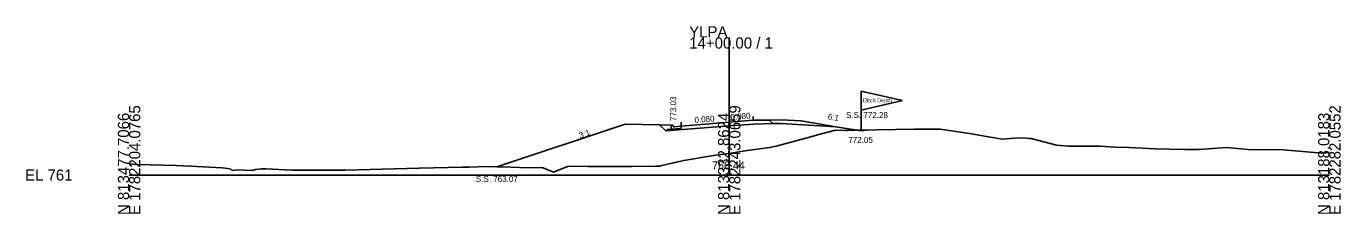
# Model space of a CAD drawing. Extents: x -76 to 1303, y -10 to 9544.
# Drawn here: x -25.7 to 302.8, y 3990.3 to 4037.3 of the extents above; entities that cross this region are included whole.
import ezdxf

# ---------------------------------------------------------------- set-up
doc = ezdxf.new("R2010")
doc.units = 0
for name, color, linetype in [('Exist Cross Section Cell', 7, 'Continuous'), ('Exist XS Center Line Elevation Label', 7, 'Continuous'), ('Exist XS Ground Line', 7, 'Continuous'), ('Prop XS Ditch Slope Text', 7, 'Continuous'), ('Prop XS Ditch Standard Text', 7, 'Continuous'), ('Prop XS Dump Level', 7, 'Continuous'), ('Prop XS Earthwork Shape', 7, 'Continuous'), ('Prop XS EOT Tick Mark', 7, 'Continuous'), ('Prop XS Finish Grade', 7, 'Continuous'), ('Prop XS Finish Grade CurbGutter', 7, 'Continuous'), ('Prop XS Finish Grade Earthwork', 7, 'Continuous'), ('Prop XS Finish Grade Paved Shoulder', 7, 'Continuous'), ('Prop XS Finish Grade Pavement', 7, 'Continuous'), ('Prop XS Hydro Elevations', 7, 'Continuous'), ('Prop XS Hydro Typical Ditch Data', 7, 'Continuous'), ('Prop XS Pvmt Edge Slope', 7, 'Continuous'), ('Prop XS SE Text', 7, 'Continuous'), ('Prop XS Side Slope Text', 7, 'Continuous'), ('Prop XS SS Elevation Text', 7, 'Continuous'), ('Prop XS Subgrade CurbGutter', 7, 'Continuous'), ('Prop XS Subgrade Earthwork', 7, 'Continuous'), ('Scratch_Level_3', 7, 'Continuous')]:
    doc.layers.add(name, color=color, linetype=linetype)

msp = doc.modelspace()

# ---------------------------------------------------------------- linework, layer by layer
at = {"layer": 'Exist Cross Section Cell'}
for p, q in [((150, 4000), (150, 4034.48)), ((0, 4000), (150, 4000)), ((150, 4000), (300, 4000))]:
    msp.add_line(p, q, dxfattribs=at)
at = {"layer": 'Exist XS Ground Line'}
for p, q in [((182.34, 4011.24), (196.26, 4011.49)), ((196.26, 4011.49), (202.73, 4011.49)), ((202.73, 4011.49), (210.09, 4010.41)), ((163.53, 4007.76), (170.42, 4009.59)), ((170.42, 4009.59), (172.42, 4010.15)), ((172.42, 4010.15), (176.59, 4011.27)), ((176.59, 4011.27), (179.29, 4011.19)), ((179.29, 4011.19), (179.65, 4011.2)), ((179.65, 4011.2), (181.12, 4011.23)), ((181.12, 4011.23), (182.34, 4011.24)), ((210.09, 4010.41), (211.52, 4010.14)), ((211.52, 4010.14), (212.37, 4010.03)), ((212.37, 4010.03), (218.21, 4008.99)), ((218.21, 4008.99), (222.31, 4009.35)), ((222.31, 4009.35), (224.19, 4009.23)), ((224.19, 4009.23), (224.9, 4009.18)), ((224.9, 4009.18), (225.5, 4009.15)), ((225.5, 4009.15), (231.81, 4007.51)), ((138.69, 4003.64), (146.6, 4004.96)), ((146.6, 4004.96), (150, 4005.44)), ((150, 4005.44), (151.02, 4005.58)), ((151.02, 4005.58), (154.46, 4006.13)), ((154.46, 4006.13), (160.16, 4006.87)), ((160.16, 4006.87), (161.71, 4007.27)), ((161.71, 4007.27), (163.53, 4007.76)), ((231.81, 4007.51), (234.8, 4007.24)), ((234.8, 4007.24), (242.66, 4007.21)), ((242.66, 4007.21), (246.56, 4007.01)), ((246.56, 4007.01), (249.92, 4006.92)), ((249.92, 4006.92), (256.58, 4006.54)), ((256.58, 4006.54), (260.05, 4006.48)), ((260.05, 4006.48), (263.88, 4006.4)), ((263.88, 4006.4), (267.34, 4006.39)), ((267.34, 4006.39), (274.27, 4006.88)), ((274.27, 4006.88), (280.6, 4006.31)), ((280.6, 4006.31), (287.51, 4006.41)), ((287.51, 4006.41), (298.23, 4005.45)), ((298.23, 4005.45), (300, 4005.63)), ((0, 4002.81), (2.13, 4002.66)), ((2.13, 4002.66), (11.7, 4002.37)), ((11.7, 4002.37), (15.31, 4002.27)), ((15.31, 4002.27), (23.3, 4001.83)), ((23.3, 4001.83), (24.7, 4001.68)), ((24.7, 4001.68), (25.41, 4001.46)), ((33.02, 4001.52), (34.15, 4001.58)), ((34.15, 4001.58), (40.74, 4001.26)), ((54.04, 4001.2), (72.5, 4001.69)), ((72.5, 4001.69), (83.32, 4001.99)), ((83.32, 4001.99), (83.88, 4002)), ((83.88, 4002), (84.93, 4002.02)), ((84.93, 4002.02), (89.53, 4002.11)), ((89.53, 4002.11), (93.35, 4002.05)), ((93.35, 4002.05), (99.64, 4001.79)), ((99.64, 4001.79), (103.25, 4001.89)), ((103.25, 4001.89), (106.05, 4000.71)), ((106.05, 4000.71), (109.56, 4002.15)), ((109.56, 4002.15), (111.52, 4002.22)), ((111.52, 4002.22), (114.63, 4002.14)), ((114.63, 4002.14), (125.63, 4002.16)), ((125.63, 4002.16), (131.57, 4002.24)), ((131.57, 4002.24), (132.57, 4002.22)), ((132.57, 4002.22), (133.14, 4002.37)), ((133.14, 4002.37), (138.69, 4003.64)), ((25.41, 4001.46), (25.73, 4001.15)), ((25.73, 4001.15), (27.05, 4001.29)), ((27.05, 4001.29), (30.74, 4001.16)), ((30.74, 4001.16), (31.61, 4001.38)), ((31.61, 4001.38), (33.02, 4001.52)), ((40.74, 4001.26), (54.04, 4001.2))]:
    msp.add_line(p, q, dxfattribs=at)
at = {"layer": 'Prop XS Dump Level'}
for p, q in [((183, 4016.25), (183, 4021.05)), ((183, 4021.05), (193.3, 4018.65)), ((193.3, 4018.65), (183, 4016.25)), ((183, 4011.05), (183, 4016.25)), ((138, 4012.27), (150, 4013.23)), ((150, 4013.23), (156, 4013.71))]:
    msp.add_line(p, q, dxfattribs=at)
at = {"layer": 'Prop XS Earthwork Shape'}
for points in [[(124, 4012.77), (91.91, 4002.07), (93.35, 4002.05), (99.64, 4001.79), (103.25, 4001.89), (106.05, 4000.71), (109.56, 4002.15), (111.52, 4002.22), (114.63, 4002.14), (125.63, 4002.16), (131.57, 4002.24), (132.57, 4002.22), (133.14, 4002.37), (138.69, 4003.64), (146.6, 4004.96), (150, 4005.44), (151.02, 4005.58), (154.46, 4006.13), (160.16, 4006.87), (161.71, 4007.27), (163.53, 4007.76), (170.42, 4009.59), (172.42, 4010.15), (176.59, 4011.27), (179.29, 4011.19), (179.65, 4011.2), (181.12, 4011.23), (181.85, 4011.24), (176.61, 4012.11), (162.98, 4012.93), (160.9, 4012.89), (156.05, 4012.79), (150.07, 4012.31), (134.16, 4011.04), (132.61, 4012.59)], [(182.34, 4011.24), (184.4, 4011.28), (183, 4011.05), (181.85, 4011.24)]]:
    msp.add_lwpolyline(points, close=True, dxfattribs=at)
at = {"layer": 'Prop XS EOT Tick Mark'}
for p, q in [((156, 4013.71), (156, 4014.71)), ((138, 4012.27), (138, 4013.27))]:
    msp.add_line(p, q, dxfattribs=at)
at = {"layer": 'Prop XS Finish Grade'}
for p, q in [((135.5, 4012.53), (132.61, 4012.59)), ((160, 4013.79), (163, 4013.85)), ((163, 4013.85), (168, 4013.55)), ((168, 4013.55), (176.61, 4012.11))]:
    msp.add_line(p, q, dxfattribs=at)
at = {"layer": 'Prop XS Finish Grade CurbGutter'}
for p, q in [((135.5, 4012.53), (135.75, 4012.53)), ((135.75, 4012.53), (135.88, 4012.51)), ((135.97, 4012.42), (135.88, 4012.51)), ((136.03, 4012.17), (135.97, 4012.42)), ((136.13, 4012.08), (136.03, 4012.17)), ((136.25, 4012.06), (136.13, 4012.08)), ((138, 4012.27), (136.25, 4012.06))]:
    msp.add_line(p, q, dxfattribs=at)
at = {"layer": 'Prop XS Finish Grade Earthwork'}
for p, q in [((124, 4012.77), (91.91, 4002.07)), ((132.61, 4012.59), (124, 4012.77)), ((176.61, 4012.11), (183, 4011.05)), ((183, 4011.05), (184.4, 4011.28))]:
    msp.add_line(p, q, dxfattribs=at)
at = {"layer": 'Prop XS Finish Grade Paved Shoulder'}
msp.add_line((156, 4013.71), (160, 4013.79), dxfattribs=at)
at = {"layer": 'Prop XS Finish Grade Pavement'}
for p, q in [((138, 4012.27), (150, 4013.23)), ((150, 4013.23), (156, 4013.71))]:
    msp.add_line(p, q, dxfattribs=at)
at = {"layer": 'Prop XS Hydro Typical Ditch Data'}
msp.add_line((183, 4011.05), (184.4, 4011.28), dxfattribs=at)
at = {"layer": 'Prop XS Pvmt Edge Slope'}
for p, q in [((134.5, 4011.41), (134.16, 4011.04)), ((135.5, 4011.49), (134.5, 4011.41)), ((160, 4013.79), (160.9, 4012.89))]:
    msp.add_line(p, q, dxfattribs=at)
at = {"layer": 'Prop XS Subgrade CurbGutter'}
for p, q in [((135.5, 4011.49), (135.5, 4012.53)), ((138, 4011.69), (135.5, 4011.49)), ((138, 4012.27), (138, 4011.69))]:
    msp.add_line(p, q, dxfattribs=at)
at = {"layer": 'Prop XS Subgrade Earthwork'}
for p, q in [((134.16, 4011.04), (132.61, 4012.59)), ((134.16, 4011.04), (150.07, 4012.31)), ((150.07, 4012.31), (156.05, 4012.79)), ((156.05, 4012.79), (160.9, 4012.89)), ((160.9, 4012.89), (162.98, 4012.93)), ((162.98, 4012.93), (176.61, 4012.11))]:
    msp.add_line(p, q, dxfattribs=at)
at = {"layer": 'Scratch_Level_3'}
for p, q in [((163, 4013.85), (160, 4013.79)), ((160, 4013.79), (160.9, 4012.89)), ((160.9, 4012.89), (162.98, 4012.93)), ((162.98, 4012.93), (176.61, 4012.11)), ((168, 4013.55), (163, 4013.85)), ((176.61, 4012.11), (168, 4013.55))]:
    msp.add_line(p, q, dxfattribs=at)

# ---------------------------------------------------------------- texts
at = {"layer": 'Exist Cross Section Cell'}
for s, p in [('YLPA', (140, 4034.48)), ('14+00.00 / 1', (140, 4031.68)), ('EL 761', (-26, 3998.6))]:
    msp.add_text(s, height=2.8, dxfattribs=at).set_placement(p)
for s, p in [('N 813477.7066', (0, 3990)), ('E 1782204.0765', (2.8, 3990)), ('N 813332.8624', (150, 3990)), ('E 1782243.0659', (152.8, 3990)), ('N 813188.0183', (300, 3990)), ('E 1782282.0552', (302.8, 3990))]:
    msp.add_text(s, height=2.8, rotation=90, dxfattribs=at).set_placement(p)
at = {"layer": 'Exist XS Center Line Elevation Label'}
msp.add_text('766.44', height=2, dxfattribs=at).set_placement((145.72, 4001.44))
at = {"layer": 'Prop XS Ditch Slope Text'}
msp.add_text('6:1', height=1.5, rotation=350.5377, dxfattribs=at).set_placement((174.55, 4013.98))
at = {"layer": 'Prop XS Ditch Standard Text'}
msp.add_text('772.05', height=1.5, dxfattribs=at).set_placement((179.77, 4008.05))
at = {"layer": 'Prop XS Dump Level'}
for s, height, p in [('Ditch Depth', 1, (183.44, 4018.22)), ('Case4', 0.04, (168, 4013.51))]:
    msp.add_text(s, height=height, dxfattribs=at).set_placement(p)
at = {"layer": 'Prop XS Hydro Elevations'}
msp.add_text('773.03', height=1.5, rotation=90, dxfattribs=at).set_placement((136.75, 4013.53))
at = {"layer": 'Prop XS SE Text'}
for p in [(141.38, 4013.04), (150.38, 4013.76)]:
    msp.add_text('0.080', height=1.5, rotation=4.5739, dxfattribs=at).set_placement(p)
at = {"layer": 'Prop XS Side Slope Text'}
msp.add_text('3:1', height=1.5, rotation=17.8228, dxfattribs=at).set_placement((112.73, 4009.18))
at = {"layer": 'Prop XS SS Elevation Text'}
for s, p in [('S.S. 772.28', (179.18, 4014.28)), ('S.S. 763.07', (86.67, 3998.28))]:
    msp.add_text(s, height=1.5, dxfattribs=at).set_placement(p)

doc.saveas('drawing.dxf')
